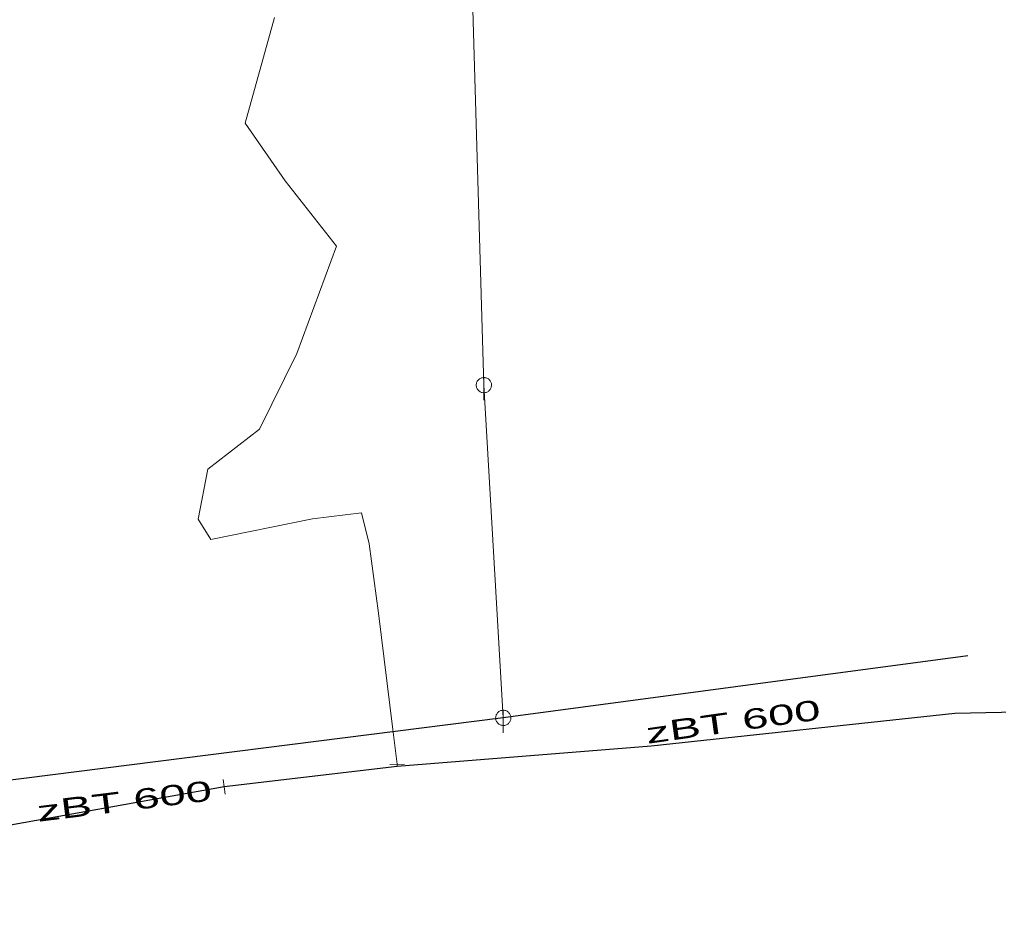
# Model space of a CAD drawing. Extents: x -687515 to -686506, y -974029 to -973461.
# Drawn here: x -686603.31 to -686570.99, y -973625.14 to -973595.01 of the extents above; entities that cross this region are included whole.
import ezdxf
from ezdxf.enums import TextEntityAlignment as Align

# ---------------------------------------------------------------- set-up
doc = ezdxf.new("R2010")
doc.units = 0
doc.header["$LTSCALE"] = 0.27
for name, color, linetype, lineweight in [('1', 7, 'Continuous', 13), ('11', 7, 'Continuous', 13), ('13', 7, 'Continuous', 13), ('14', 7, 'Continuous', 25), ('17', 7, 'Continuous', 25), ('22', 7, 'Continuous', 13), ('34', 7, 'Continuous', 13)]:
    doc.layers.add(name, color=color, linetype=linetype, lineweight=lineweight)

msp = doc.modelspace()

# ---------------------------------------------------------------- linework, layer by layer
at = {"layer": '11'}
msp.add_line((-686587.976, -973607.074), (-686587.336, -973618.056), dxfattribs=at)
msp.add_lwpolyline([(-686581.88, -973576.653), (-686582.507, -973578.357), (-686583.54, -973578.061), (-686588.42, -973592.039), (-686587.976, -973607.074)], dxfattribs=at)
at = {"layer": '13'}
msp.add_lwpolyline([(-686590.839, -973619.589), (-686590.985, -973618.443), (-686591.459, -973614.604), (-686591.76, -973612.31), (-686592.014, -973611.286), (-686593.634, -973611.484), (-686596.991, -973612.167), (-686597.404, -973611.5), (-686597.094, -973609.849), (-686595.388, -973608.524), (-686594.155, -973606.026), (-686592.843, -973602.491), (-686594.536, -973600.332), (-686595.859, -973598.427), (-686594.888, -973594.937)], dxfattribs=at)
at = {"layer": '14'}
for p, q in [((-686571.995, -973616.005), (-686587.336, -973618.056)), ((-686587.336, -973618.056), (-686612.187, -973621.194))]:
    msp.add_line(p, q, dxfattribs=at)
at = {"layer": '14', "lineweight": 13}
msp.add_line((-686590.836, -973619.663), (-686590.839, -973619.589), dxfattribs=at)
at = {"layer": '17'}
msp.add_line((-686596.546, -973620.333), (-686623.461, -973625.138), dxfattribs=at)
msp.add_lwpolyline([(-686534.409, -973617.099), (-686572.422, -973617.914), (-686582.448, -973618.993), (-686590.836, -973619.663), (-686596.546, -973620.333)], dxfattribs=at)
at = {"layer": '22'}
for p, q in [((-686587.975, -973606.822), (-686587.976, -973607.566)), ((-686587.335, -973617.804), (-686587.336, -973618.548))]:
    msp.add_line(p, q, dxfattribs=at)
for points in [[(-686587.724, -973607.074), (-686587.725, -973607.048), (-686587.729, -973607.022), (-686587.735, -973606.996), (-686587.745, -973606.972), (-686587.757, -973606.948), (-686587.771, -973606.926), (-686587.788, -973606.905), (-686587.806, -973606.887), (-686587.827, -973606.87), (-686587.849, -973606.856), (-686587.873, -973606.844), (-686587.897, -973606.834), (-686587.923, -973606.828), (-686587.949, -973606.824), (-686587.975, -973606.822), (-686588.001, -973606.823), (-686588.027, -973606.827), (-686588.053, -973606.833), (-686588.078, -973606.843), (-686588.101, -973606.855), (-686588.123, -973606.869), (-686588.144, -973606.886), (-686588.162, -973606.904), (-686588.179, -973606.925), (-686588.193, -973606.947), (-686588.205, -973606.971), (-686588.215, -973606.995), (-686588.222, -973607.021), (-686588.226, -973607.047), (-686588.228, -973607.073), (-686588.227, -973607.099), (-686588.223, -973607.125), (-686588.216, -973607.151), (-686588.206, -973607.176), (-686588.194, -973607.199), (-686588.18, -973607.221), (-686588.163, -973607.242), (-686588.145, -973607.26), (-686588.124, -973607.277), (-686588.102, -973607.291), (-686588.079, -973607.303), (-686588.054, -973607.313), (-686588.028, -973607.32), (-686588.002, -973607.324), (-686587.976, -973607.326), (-686587.95, -973607.325), (-686587.924, -973607.321), (-686587.898, -973607.314), (-686587.874, -973607.304), (-686587.85, -973607.292), (-686587.828, -973607.278), (-686587.807, -973607.261), (-686587.789, -973607.243), (-686587.772, -973607.222), (-686587.758, -973607.2), (-686587.746, -973607.177), (-686587.736, -973607.152), (-686587.73, -973607.126), (-686587.726, -973607.1)], [(-686587.084, -973618.056), (-686587.085, -973618.03), (-686587.089, -973618.004), (-686587.095, -973617.978), (-686587.105, -973617.954), (-686587.117, -973617.93), (-686587.131, -973617.908), (-686587.148, -973617.887), (-686587.166, -973617.869), (-686587.187, -973617.852), (-686587.209, -973617.838), (-686587.233, -973617.826), (-686587.257, -973617.816), (-686587.283, -973617.81), (-686587.309, -973617.806), (-686587.335, -973617.804), (-686587.361, -973617.805), (-686587.387, -973617.809), (-686587.413, -973617.815), (-686587.438, -973617.825), (-686587.461, -973617.837), (-686587.483, -973617.851), (-686587.504, -973617.868), (-686587.522, -973617.886), (-686587.539, -973617.907), (-686587.553, -973617.929), (-686587.565, -973617.953), (-686587.575, -973617.977), (-686587.582, -973618.003), (-686587.586, -973618.029), (-686587.588, -973618.055), (-686587.587, -973618.081), (-686587.583, -973618.107), (-686587.576, -973618.133), (-686587.566, -973618.158), (-686587.554, -973618.181), (-686587.54, -973618.203), (-686587.523, -973618.224), (-686587.505, -973618.242), (-686587.484, -973618.259), (-686587.462, -973618.273), (-686587.439, -973618.285), (-686587.414, -973618.295), (-686587.388, -973618.302), (-686587.362, -973618.306), (-686587.336, -973618.308), (-686587.31, -973618.307), (-686587.284, -973618.303), (-686587.258, -973618.296), (-686587.234, -973618.286), (-686587.21, -973618.274), (-686587.188, -973618.26), (-686587.167, -973618.243), (-686587.149, -973618.225), (-686587.132, -973618.204), (-686587.118, -973618.182), (-686587.106, -973618.159), (-686587.096, -973618.134), (-686587.09, -973618.108), (-686587.086, -973618.082)]]:
    msp.add_lwpolyline(points, close=True, dxfattribs=at)
at = {"layer": '34'}
for p, q in [((-686590.591, -973619.579), (-686591.086, -973619.598)), ((-686596.513, -973620.578), (-686596.578, -973620.087))]:
    msp.add_line(p, q, dxfattribs=at)

# ---------------------------------------------------------------- texts
at = {"layer": '1', "width": 1.75}
for rotation, p in [(8, (-686579.486, -973618.479)), (7, (-686599.591, -973621.106))]:
    msp.add_text('zBT 600 ', height=0.6667, rotation=rotation, dxfattribs=at).set_placement(p, align=Align.CENTER)

doc.saveas('drawing.dxf')
